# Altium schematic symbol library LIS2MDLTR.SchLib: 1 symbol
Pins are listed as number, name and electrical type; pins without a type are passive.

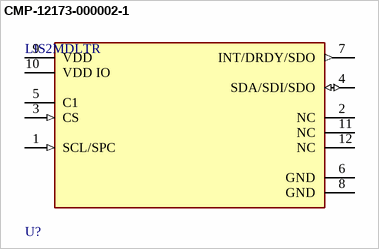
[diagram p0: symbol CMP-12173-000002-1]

## CMP-12173-000002-1
designator U?, comment LIS2MDLTR
SENSOR MR I2C/SPI 12LGA; Manufacturer: STMicroelectronics; Sensing Method: Magnetic; Min Supply Voltage: 1.71V; Sensor Output: I2C,SPI; Operating Supply Current: 50-200uA; Max Supply Voltage: 3.6V
footprint FP-LGA-12-DM00170568-MFG
pins: 1 SCL/SPC (in), 2 NC, 3 CS (in), 4 SDA/SDI/SDO (io), 5 C1, 6 GND (power), 7 INT/DRDY/SDO (out), 8 GND (power), 9 VDD (power), 10 VDD IO (power), 11 NC, 12 NC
